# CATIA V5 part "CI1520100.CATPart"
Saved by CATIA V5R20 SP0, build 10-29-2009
Part number: CI1520100
Bounding box of the stored display mesh (mm): x -19 to 19, y -15.149 to 130, z -23.548 to 21.957
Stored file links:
  C:\Users\Raffaele\Desktop\3D X SITO CF\BOLEX\19-INCLINED ASSEMBLY REF_CI\CI1520100.CATPart

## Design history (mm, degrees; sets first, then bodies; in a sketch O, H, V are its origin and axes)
Set1
  DatumSurface1 to DatumSurface16 "MANIFOLD_SOLID_BREP #385"
  DatumSurface17 to DatumSurface39 "MANIFOLD_SOLID_BREP #1114"
Body1 (main body)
